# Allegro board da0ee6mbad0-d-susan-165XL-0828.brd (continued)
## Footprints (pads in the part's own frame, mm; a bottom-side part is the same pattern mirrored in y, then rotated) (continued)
CARD-CH1S-131-H-N-12P
  rect 0.66x0.991 smd: 1(2.6,9.6) 2(1.7,9.6) 3(0.8,9.6) 4(-0.1,9.6) 5(-1,9.6) 6(-1.9,9.6) 7(-2.8,9.6) 8(-3.7,9.6)
  rect 0.889x0.991 smd: 9(-5.3,9.6)
  rect 1.194x1.295 smd: 10(7.3,2.7)
  rect 0.991x1.702 smd: 11(7.2,9.25) 12(-7.2,9.25)
  oval 1.092x1.803 hole 0.508x1.194: 13(6.83,0) 14(-6.82,0)
CC0201_S
  rect 0.254x0.356 smd: 1(0.24,0) 2(-0.24,0)
CC0402
  custom 0.12x0.12 smd: 1(0.39,0) 2(-0.39,0)
CC0402_S
  rect 0.508x0.508 smd: 1(-0.42,0) 2(0.42,0)
CC0603
  rect 0.813x0.711 smd: 1(0.737,0) 2(-0.737,0)
CC0805
  rect 0.94x1.346 smd: 1(0.895,0) 2(-0.895,0)
CC1206
  rect 1.6x1.6 smd: 1(1.702,0) 2(-1.702,0)
CC3528
  rect 2.032x2.413 smd: 1(1.6,0) 2(-1.6,0)
CHOKE-1124BS-3R3M
  rect 0.991x2.21 smd: 1(-2.15,0) 2(2.15,0)
CHOKE-MMD-05AH-4R7M-X2Q
  rect 1.905x2.794 smd: 1(-2.038,0) 2(2.038,0)
CHOKE-WCM2012-4P
  rect 0.889x0.406 smd: 1(-0.85,0.4) 2(0.85,0.4) 3(0.85,-0.4) 4(-0.85,-0.4)
D-0_9X0_6
  rect 0.559x0.457 smd: 1(0,-0.475) 2(0,0.475)
D-2_8X1_78
  rect 2.21x1.397 smd: 1(-0.95,0)
  rect 0.889x1.397 smd: 2(1.6,0)
DFN6-1_5X1-5
  rect 0.254x0.991 smd: 1(-0.5,-0.567)
  rect 0.254x0.914 smd: 2(0,-0.605) 3(0.5,-0.605) 4(0.5,0.605) 5(0,0.605) 6(-0.5,0.605)
DSM
  rect 1.016x0.508 smd: 1(-1.3,0) 2(1.321,0)
DSMV
  rect 0.762x1.016 smd: 1(0,1.27) 2(0,-1.27)
EE6-SHIELDING-6
  custom 8.473x8.473 smd: 1(0,0)
EE6-SHIELDING-7
  custom 3.4x3.4 smd: 1(0,0)
EE6-SHIELDING-8
  custom 4.193x4.193 smd: 1(0,0)
EE6-SHIELDING-10
  custom 3.452x3.452 smd: 1(0,0)
  custom 0.421x0.421 smd: 2(-7.352,-14.478)
EE6-SHIELDING-11
  custom 12.781x12.781 smd: 1(0,0)
EMIPAD63X56
  custom 0.358x0.358 smd: 1(0,0)
EMIPAD98X79
  rect 2.489x2.007 smd: 1(0,0)
FH34SRJ-6S-0_5SH-6P-L
  rect 0.305x0.787 smd: 1(-1.25,2.5) 2(-0.75,2.5) 3(-0.25,2.5) 4(0.25,2.5) 5(0.75,2.5) 6(1.25,2.5)
  rect 0.406x0.787 smd: 7(-2.25,0) 8(2.25,0)
FH35C-21S-0_3SHW-21P-LDH
  rect 0.305x0.787 smd: 1(-3,-1.475) 2(-2.4,-1.475) 3(-1.8,-1.475) 4(-1.2,-1.475) 5(-0.6,-1.475) 6(0,-1.475) 7(0.6,-1.475) 8(1.2,-1.475) 9(1.8,-1.475) 10(2.4,-1.475) 11(3,-1.475)
  rect 0.305x0.66 smd: 12(2.7,1.4) 13(2.1,1.4) 14(1.5,1.4) 15(0.9,1.4) 16(0.3,1.4) 17(-0.3,1.4) 18(-0.9,1.4) 19(-1.5,1.4) 20(-2.1,1.4) 21(-2.7,1.4)
  rect 0.406x0.94 smd: 22(-3.7,-1.2) 23(3.7,-1.2)
FH35C-31S-0_3SHW-31P-LDH
  rect 0.305x0.787 smd: 1(-4.5,-1.475) 2(-3.9,-1.475) 3(-3.3,-1.475) 4(-2.7,-1.475) 5(-2.1,-1.475) 6(-1.5,-1.475) 7(-0.9,-1.475) 8(-0.3,-1.475) 9(0.3,-1.475) 10(0.9,-1.475) 11(1.5,-1.475) 12(2.1,-1.475) 13(2.7,-1.475) 14(3.3,-1.475) 15(3.9,-1.475) 16(4.5,-1.475)
  rect 0.305x0.66 smd: 17(4.2,1.4) 18(3.6,1.4) 19(3,1.4) 20(2.4,1.4) 21(1.8,1.4) 22(1.2,1.4) 23(0.6,1.4) 24(0,1.4) 25(-0.6,1.4) 26(-1.2,1.4) 27(-1.8,1.4) 28(-2.4,1.4) 29(-3,1.4) 30(-3.6,1.4) 31(-4.2,1.4)
  rect 0.406x0.94 smd: 32(-5.2,-1.2) 33(5.2,-1.2)
FILTER-LXES11DAA2-135-6P
  rect 0.305x0.508 smd: 1(0.275,0.625) 2(-0.275,0.625) 4(-0.275,-0.625) 5(0.275,-0.625)
  rect 0.406x0.203 smd: 3(-0.5,0) 6(0.5,0)
FILTER-SAFEA1G57KH0F00-5P
  rect 0.432x0.33 smd: 1(-0.588,0) 3(0.588,-0.288) 4(0.588,0.288)
  rect 0.254x0.533 smd: 2(0,-0.388) 5(0,0.388)
H-C71D71N
  round 1.803 hole 1.803 unplated: (0,0)
H-C197D79P2
  round 5.004 hole 2.007: 1(0,0)
H-C236D79P2
  round 5.994 hole 2.007: 1(0,0)
HDMI-46765-1301-19P
  rect 0.203x0.838 smd: 1(1.8,4.775) 3(1.4,4.775) 5(1,4.775) 7(0.6,4.775) 9(0.2,4.775) 11(-0.2,4.775) 13(-0.6,4.775) 15(-1,4.775) 17(-1.4,4.775) 19(-1.8,4.775)
  rect 0.203x0.991 smd: 2(1.6,3.55) 4(1.2,3.55) 6(0.8,3.55) 8(0.4,3.55) 10(0,3.55) 12(-0.4,3.55) 14(-0.8,3.55) 16(-1.2,3.55) 18(-1.6,3.55)
  oval 1.499x2.54 hole 0.66x1.702: 20(3.1,3.36) 21(3.1,0) 22(-3.1,3.36) 23(-3.1,0)
L2X1_6-1_6-1H
  rect 0.787x1.803 smd: 1(-0.8,0) 2(0.8,0)
L2X1_6-1H
  rect 0.787x1.803 smd: 1(-0.8,0) 2(0.8,0)
LED12-22-BXY2P-C31-2C-3P
  rect 0.991x1.499 smd: 1(1.5,-0.05) 3(-1.5,-0.05)
  rect 0.889x0.889 smd: 2(0,-0.7)
LEDLTW-C191DS5
  rect 0.787x0.787 smd: 1(0,-0.75) 2(0,0.75)
LGA14-5X3-8
  rect 0.61x1.397 smd: 1(2,1.3) 2(1.2,1.3) 3(0.4,1.3) 4(-0.4,1.3) 5(-1.2,1.3) 6(-2,1.3) 8(-2,-1.3) 9(-1.2,-1.3) 10(-0.4,-1.3) 11(0.4,-1.3) 12(1.2,-1.3) 13(2,-1.3)
  rect 1.702x0.635 smd: 7(-2.15,0) 14(2.15,0)
LGA16-4X4-65
  rect 0.991x0.381 smd: 1(-2,0.975) 2(-2,0.325) 3(-2,-0.325) 4(-2,-0.975) 9(2,-0.975) 10(2,-0.325) 11(2,0.325) 12(2,0.975)
  rect 0.381x0.991 smd: 5(-0.975,-2) 6(-0.325,-2) 7(0.325,-2) 8(0.975,-2) 13(0.975,2) 14(0.325,2) 15(-0.325,2) 16(-0.975,2)
MIC-MP45DT02TR-6P
  round 0.914 smd: 1(-1.175,1.65) 2(-1.175,0) 3(-1.175,-1.65) 4(1.175,-1.65) 5(1.175,0)
  oval 0.914x1.194 smd rot 135: 6(1.07,1.55)
MIPCI-APCI0026-P001A-75P-KB
  round 1.092 hole 1.092 unplated: (-11,0)
  round 1.6 hole 1.6 unplated: (11,0)
  rect 0.305x1.499 smd: 1(-9.25,1.55) 2(-9,-1.09) 3(-8.75,1.55) 4(-8.5,-1.09) 5(-8.25,1.55) 6(-8,-1.09) 7(-7.75,1.55) 8(-7.5,-1.09) 9(-7.25,1.55) 10(-7,-1.09) 11(-6.75,1.55) 20(-4.5,-1.09) 21(-4.25,1.55) 22(-4,-1.09) 23(-3.75,1.55) 24(-3.5,-1.09) 25(-3.25,1.55) 26(-3,-1.09) 27(-2.75,1.55) 28(-2.5,-1.09) 29(-2.25,1.55) 30(-2,-1.09) 31(-1.75,1.55) 32(-1.5,-1.09) 33(-1.25,1.55) 34(-1,-1.09) 35(-0.75,1.55) 36(-0.5,-1.09) 37(-0.25,1.55) 38(0,-1.09) 39(0.25,1.55) 40(0.5,-1.09) 41(0.75,1.55) 42(1,-1.09) 43(1.25,1.55) 44(1.5,-1.09) 45(1.75,1.55) 46(2,-1.09) 47(2.25,1.55) 48(2.5,-1.09) 49(2.75,1.55) 50(3,-1.09) 51(3.25,1.55) 52(3.5,-1.09) 53(3.75,1.55) 54(4,-1.09) 55(4.25,1.55) 56(4.5,-1.09) 57(4.75,1.55) 58(5,-1.09) 59(5.25,1.55) 60(5.5,-1.09) 61(5.75,1.55) 62(6,-1.09) 63(6.25,1.55) 64(6.5,-1.09) 65(6.75,1.55) 66(7,-1.09) 67(7.25,1.55) 68(7.5,-1.09) 69(7.75,1.55) 70(8,-1.09) 71(8.25,1.55) 72(8.5,-1.09) 73(8.75,1.55) 74(9,-1.09) 75(9.25,1.55)
  rect 1.194x2.743 smd: 76(-11.385,-4.97) 77(11.385,-4.97)
O-EE6-1
  custom 1.913x1.913 hole 1.803: 1(0,0)
O-EE6-2
  custom 1.5x1.5 hole 1.803: 1(0,0)
O-EE6-3
  custom 1.5x1.5 hole 2.007: 1(0,0)
O-EE6-5
  round 2.54 hole 2.54 unplated: (0,0)
OPLGA6-2_35X1_8-6
  rect 0.991x0.406 smd: 1(-1.125,0.6) 2(-1.125,0) 3(-1.125,-0.6) 4(1.125,-0.6) 5(1.125,0) 6(1.125,0.6)
PG-TSDSON-8-8P-R
  rect 0.787x0.33 smd: 1(1.5,-0.975) 2(1.5,-0.325) 3(1.5,0.325) 4(1.5,0.975)
  custom 0.573x0.573 smd: 5(-0.72,0)
  rect 0.66x0.33 smd: 6(-1.575,0.325) 7(-1.575,-0.325) 8(-1.575,-0.975)
POWER-3_3X3_3-65-5P-SMT
  rect 0.432x0.762 smd: 1(-0.975,-1.43) 2(-0.325,-1.43) 3(0.325,-1.43) 4(0.975,-1.43)
  custom 0.562x0.562 smd: 5(0,0.725)
QFN10-3X3-5-11P
  rect 0.305x0.991 smd: 1(-1,-1.6) 2(-0.5,-1.6) 3(0,-1.6) 4(0.5,-1.6) 5(1,-1.6) 6(1,1.6) 7(0.5,1.6) 8(0,1.6) 9(-0.5,1.6) 10(-1,1.6)
  custom 0.413x0.413 smd: 11(0,0)
QFN16-3X3-5-17P-TPS61176RTE
  custom 0.07x0.07 smd: 1(-0.75,-1.475) 2(-0.25,-1.475) 3(0.25,-1.475) 4(0.75,-1.475) 5(1.475,-0.75) 6(1.475,-0.25) 7(1.475,0.25) 8(1.475,0.75) 9(0.75,1.475) 10(0.25,1.475) 11(-0.25,1.475) 12(-0.75,1.475) 13(-1.475,0.75) 14(-1.475,0.25) 15(-1.475,-0.25) 16(-1.475,-0.75)
  rect 1.651x1.651 smd: 17(0,0)
QFN24-4X4-5-34P
  rect 0.838x0.279 smd: 1(-1.975,1.25) 2(-1.975,0.75) 3(-1.975,0.25) 4(-1.975,-0.25) 5(-1.975,-0.75) 6(-1.975,-1.25) 13(1.975,-1.25) 14(1.975,-0.75) 15(1.975,-0.25) 16(1.975,0.25) 17(1.975,0.75) 18(1.975,1.25)
  rect 0.279x0.838 smd: 7(-1.25,-1.975) 8(-0.75,-1.975) 9(-0.25,-1.975) 10(0.25,-1.975) 11(0.75,-1.975) 12(1.25,-1.975) 19(1.25,1.975) 20(0.75,1.975) 21(0.25,1.975) 22(-0.25,1.975) 23(-0.75,1.975) 24(-1.25,1.975)
  rect 2.692x2.692 smd: 25(0,0)
  round 0.61 hole 0.305: 26(-0.9,0.9) 27(-0.9,0) 28(-0.9,-0.9) 29(0,-0.9) 30(0.9,-0.9) 31(0.9,0) 32(0.9,0.9) 33(0,0.9) 34(0,0)
QFN48-6X6-4-49P-ALC280
  rect 0.991x0.203 smd: 1(-3.1,2.2) 2(-3.1,1.8) 3(-3.1,1.4) 4(-3.1,1) 5(-3.1,0.6) 6(-3.1,0.2) 7(-3.1,-0.2) 8(-3.1,-0.6) 9(-3.1,-1) 10(-3.1,-1.4) 11(-3.1,-1.8) 12(-3.1,-2.2) 25(3.1,-2.2) 26(3.1,-1.8) 27(3.1,-1.4) 28(3.1,-1) 29(3.1,-0.6) 30(3.1,-0.2) 31(3.1,0.2) 32(3.1,0.6) 33(3.1,1) 34(3.1,1.4) 35(3.1,1.8) 36(3.1,2.2)
  rect 0.203x0.991 smd: 13(-2.2,-3.1) 14(-1.8,-3.1) 15(-1.4,-3.1) 16(-1,-3.1) 17(-0.6,-3.1) 18(-0.2,-3.1) 19(0.2,-3.1) 20(0.6,-3.1) 21(1,-3.1) 22(1.4,-3.1) 23(1.8,-3.1) 24(2.2,-3.1) 37(2.2,3.1) 38(1.8,3.1) 39(1.4,3.1) 40(1,3.1) 41(0.6,3.1) 42(0.2,3.1) 43(-0.2,3.1) 44(-0.6,3.1) 45(-1,3.1) 46(-1.4,3.1) 47(-1.8,3.1) 48(-2.2,3.1)
  rect 4.394x4.394 smd: 49(0,0)
QFN48-7X7-5-49P-STM32F103CB
  rect 0.559x0.305 smd: 1(-3.375,2.75) 2(-3.375,2.25) 3(-3.375,1.75) 4(-3.375,1.25) 5(-3.375,0.75) 6(-3.375,0.25) 7(-3.375,-0.25) 8(-3.375,-0.75) 9(-3.375,-1.25) 10(-3.375,-1.75) 11(-3.375,-2.25) 12(-3.375,-2.75) 25(3.375,-2.75) 26(3.375,-2.25) 27(3.375,-1.75) 28(3.375,-1.25) 29(3.375,-0.75) 30(3.375,-0.25) 31(3.375,0.25) 32(3.375,0.75) 33(3.375,1.25) 34(3.375,1.75) 35(3.375,2.25) 36(3.375,2.75)
  rect 0.305x0.559 smd: 13(-2.75,-3.375) 14(-2.25,-3.375) 15(-1.75,-3.375) 16(-1.25,-3.375) 17(-0.75,-3.375) 18(-0.25,-3.375) 19(0.25,-3.375) 20(0.75,-3.375) 21(1.25,-3.375) 22(1.75,-3.375) 23(2.25,-3.375) 24(2.75,-3.375) 37(2.75,3.375) 38(2.25,3.375) 39(1.75,3.375) 40(1.25,3.375) 41(0.75,3.375) 42(0.25,3.375) 43(-0.25,3.375) 44(-0.75,3.375) 45(-1.25,3.375) 46(-1.75,3.375) 47(-2.25,3.375) 48(-2.75,3.375)
  rect 5.588x5.588 smd: 49(0,0)
RC0201_S
  rect 0.254x0.356 smd: 1(0.24,0) 2(-0.24,0)
RC0402
  custom 0.12x0.12 smd: 1(0.39,0) 2(-0.39,0)
RC0402_S
  rect 0.508x0.508 smd: 1(-0.42,0) 2(0.42,0)
RC0603
  rect 0.813x0.711 smd: 1(0.737,0) 2(-0.737,0)
RC0805_S
  rect 0.864x1.372 smd: 1(-0.88,0) 2(0.88,0)
RC3216
  rect 3.2x0.94 smd: 1(0,0.825) 2(0,-0.825)
SC70-2_1-65-6P
  rect 1.27x0.279 smd: 1(1.02,-0.65) 2(1.02,0) 3(1.02,0.65) 4(-1.02,0.65) 5(-1.02,0) 6(-1.02,-0.65)
SHORT0201_S
  rect 0.432x0.356 smd: 1(0.24,0) 2(-0.24,0)
SHORT0402
  rect 0.648x0.5 smd: 1(-0.39,0) 2(0.39,0)
SHORT0402_S
  rect 0.737x0.508 smd: 1(-0.42,0) 2(0.42,0)
SHORT0603
  rect 1.219x0.711 smd: 1(0.737,0) 2(-0.737,0)
SHORT0805
  rect 1.422x1.346 smd: 1(0.895,0) 2(-0.895,0)
SIMCARD-159-1000302603-10P-L
  round 0.889 hole 0.889 unplated: (4.94,7.9) (5.64,-3.2)
  rect 0.508x1.245 smd: 1(-3.545,9.325) 2(-2.845,9.325) 3(-2.145,9.325) 4(-1.445,9.325) 5(-0.745,9.325) 6(-0.045,9.325) 7(0.655,9.325) 8(1.355,9.325) 9(2.055,9.325) 10(2.755,9.325)
  rect 0.889x1.397 smd: 11(5.41,9.4) 18(-4.7,9.4)
  rect 0.381x1.6 smd: 12(7.165,6.85)
  rect 0.381x1.499 smd: 13(7.165,0) 16(-7.165,0)
  rect 1.092x1.092 smd: 14(6.8,-5.32) 15(-6.8,-5.32)
  rect 0.381x1.245 smd: 17(-7.165,6.24)
SOIC8-8-1_27
  rect 0.533x1.6 smd: 1(1.905,3.8) 2(0.635,3.8) 3(-0.635,3.8) 4(-1.905,3.8) 5(-1.905,-3.8) 6(-0.635,-3.8) 7(0.635,-3.8) 8(1.905,-3.8)
SOT23-2_8-95-5P-1_45H
  rect 0.508x1.321 smd: 1(-0.95,-1.338) 2(0,-1.338) 3(0.95,-1.338) 4(0.95,1.338) 5(-0.95,1.338)
SOT23-5
  rect 1.016x0.711 smd: 1(1.2,-0.95) 2(1.2,0) 3(1.2,0.95) 4(-1.2,0.95) 5(-1.2,-0.95)
SOT23-5-2_8-95-5P-1_3H
  rect 1.194x0.533 smd: 1(1.5,-0.95) 2(1.5,0) 3(1.5,0.95) 4(-1.5,0.95) 5(-1.5,-0.95)
SOT23_123-2_8-1_9
  rect 1.092x0.533 smd: 1(1.45,-0.95) 2(1.45,0.95) 3(-1.45,0)
SOT23_213-3_3-2
  rect 1.27x1.016 smd: 1(1.016,1.016) 2(1.016,-1.016) 3(-1.016,0)
SW-MTA-NC-V-T-R-5P
  round 0.889 hole 0.889 unplated: (-2.15,0) (2.15,0)
  custom 0.178x0.178 smd: 1(2.1,0.95) 2(-2.1,0.95)
  rect 0.711x1.194 smd: 3(1.7,-1.3) 5(-1.7,-1.3)
  rect 1.295x0.787 smd: 4(0,-1.5)
TDFN8-3X3-65-9P
  rect 0.381x0.94 smd: 1(-0.975,-1.625) 2(-0.325,-1.625) 3(0.325,-1.625) 4(0.975,-1.625) 5(0.975,1.625) 6(0.325,1.625) 7(-0.325,1.625) 8(-0.975,1.625)
  rect 2.311x1.499 smd: 9(0,0)
TP2050
  round 0.508 smd: 1(0,0)
TP2650
  round 0.66 smd: 1(0,0)
TQFN10-1_6X1_3-4
  rect 0.203x0.711 smd: 1(0.2,0.46) 2(-0.2,0.46) 6(-0.2,-0.46) 7(0.2,-0.46)
  rect 0.508x0.203 smd: 3(-0.735,0.4) 4(-0.735,0) 5(-0.735,-0.4) 8(0.735,-0.4) 9(0.735,0) 10(0.735,0.4)
UFDFPN8-2X3-5-9P
  rect 0.305x1.194 smd: 1(-0.75,-1.35) 2(-0.25,-1.35) 3(0.25,-1.35) 4(0.75,-1.35) 5(0.75,1.35) 6(0.25,1.35) 7(-0.25,1.35) 8(-0.75,1.35)
  rect 1.6x0.203 smd: 9(0,0)
unnamed
  round 1.016 smd: 1(0,0)
UQFN10-2X1_5-5-0_6H
  rect 0.305x0.584 smd: 1(-0.75,-0.638) 4(0.75,-0.638) 6(0.75,0.638) 9(-0.75,0.638)
  rect 0.254x0.584 smd: 2(-0.25,-0.638) 3(0.25,-0.638) 7(0.25,0.638) 8(-0.25,0.638)
  rect 0.635x0.356 smd: 5(0.86,0) 10(-0.86,0)
VMT3-1_2-8
  rect 0.457x0.406 smd: 1(0.575,-0.4) 2(0.575,0.4)
  rect 0.508x0.457 smd: 3(-0.575,0)
VSSOP8-3_1-5-8P
  rect 0.203x1.168 smd: 1(-0.75,-1.563) 2(-0.25,-1.563) 3(0.25,-1.563) 4(0.75,-1.563) 5(0.75,1.563) 6(0.25,1.563) 7(-0.25,1.563) 8(-0.75,1.563)
XTL-2_1X1_7-1_94X1_19
  rect 0.432x0.787 smd: 1(-0.97,-0.595) 2(0.97,-0.595) 3(0.97,0.595) 4(-0.97,0.595)
XTL-3_2X1_5-2_5-0_8H
  rect 0.991x1.803 smd: 1(-1.25,0) 2(1.25,0)
XTL-3_2X2_5-2_2X1_7
  rect 1.397x1.194 smd: 1(1.1,0.85) 2(-1.1,0.85) 3(-1.1,-0.85) 4(1.1,-0.85)
XTL-3_2X2_5-2_2X1_7-4P
  rect 1.397x1.194 smd: 1(1.1,0.85) 2(-1.1,0.85) 3(-1.1,-0.85) 4(1.1,-0.85)

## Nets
+1.8V_EMMC: C8.2 C188.2 C196.2 C200.1 C204.1 R275.2 U26.AA3 U26.AA5 U26.K6 U26.W4 U26.Y4
+1V: PC45.2 PQ8.1 PQ8.2 PQ8.3 PR58.2 PR63.1 PR64.1 PR65.1 PR81.2 PR83.1 PR84.1 PR666.1 R56.2 R77.1 R297.2 R327.1
+1V05: PC94.1 PL13.1 PU5.P8 R292.1 R295.1
+1V05_SOC: C27.1 C30.1 C259.1 C261.1 C263.1 R292.2 R295.2 U29.A30 U29.A33 U29.A35 U29.AC37 U29.AD36 U29.AK39 U29.B36 U29.BW39 U29.W39
+1V8: C298.1 C319.1 C375.1 CN2.9 L5.2 PC17.1 PR1.1 PR96.1 PR109.1 PR110.1 PR111.1 PR112.1 PU5.B9 Q2.1 Q3.1 Q7.2 Q8.2 Q17.1 R14.1 R15.1 R47.1 R53.1 R73.1 R74.1 R80.1 R93.2 R115.1 R117.2 R119.2 R160.1 R168.2 R170.2 R175.2 R177.2 R183.2 R187.1 R262.2 R275.1 R290.1 R291.1 R293.1 R303.2 R305.2 R335.2 R337.1 R340.2 R342.2 R345.2 R353.1 R359.2 R362.2 U31.2 U33.2 U37.2
+1V8_SOC: C26.1 C31.1 C262.1 C269.1 R47.2 U29.BF36 U29.BV22 U29.BV32 U29.BW21 U29.BW33 U29.P42
+1V8S5: C25.2 C77.2 PC15.1 PC82.2 PC83.2 PC84.2 PL12.2 PR20.2 PU5.B8 PU5.C9 PU5.G1 R17.1 R18.1 R26.2 R27.1 R29.1 R37.2 R38.1 R41.1 R46.1 R84.2 R134.2 R135.2 R136.2 R166.1 R298.2 R302.2 R313.1 R328.2 R332.2 R333.2 U3.C2 U5.A2
+1V8S5_SOC: C43.1 C47.1 C67.1 C282.1 R37.1 R306.2 R307.2 R402.2 U29.AD15 U29.G1 U29.P21 U29.P23 U29.P27
+1V8SX: PC9.1 PR44.1 PU5.B7 R1.2 R216.1 R220.1 R223.1 R230.2
+1V24: PC77.1 PU5.C10 R70.1 R71.1 R315.2
+1V24_SOC: C277.1 R315.1 U29.AF2 U29.AG1
+1V24S5: PC70.1 PU5.C7 R320.2
+1V24S5_SOC: C284.1 R320.1 U29.R1
+1V24SX: PC23.1 PU5.B10 R76.1 R81.1 R82.1
+1V24SX_SOC: C21.1 R76.2 U29.AK45
+1V_SOC: C32.1 C35.1 C62.1 C278.1 C280.1 C281.1 C283.1 C286.1 C289.1 R327.2 U29.AA1 U29.AN1 U29.AP2 U29.BF32 U29.M36 U29.N1 U29.P2
+1VS5: PC18.1 PC47.2 PC48.2 PC53.2 PC97.1 PC98.1 PL15.1 PQ7.5 PQ8.5 PQ9.5 PU5.C11 PU5.M10 R78.1
+1VS5_SOC: C59.1 C64.1 C285.1 R78.2 U29.P15 U29.P17 U29.P19 U29.T18 U29.W1
+1VSX: C72.1 C73.1 C74.1 PC46.2 PQ9.1 PQ9.2 PQ9.3 PR60.2 R59.1 R299.1 R300.1 R667.1
+1VSX_S: PC44.2 PQ7.1 PQ7.2 PQ7.3 PR666.2 R309.1 R310.1 R667.2
+1VSX_S_SOC: C24.2 C255.1 C256.1 C257.1 C258.1 R309.2 R310.2 U29.A41 U29.A43 U29.AC43 U29.AH44 U29.AW44 U29.B40 U29.BV40 U29.BW41 U29.BW43
+1VSX_SOC: C61.1 C264.2 C265.1 C272.1 C273.1 C279.1 R299.2 R300.2 U29.A9 U29.A13 U29.AT19 U29.AT21 U29.AV2 U29.AW1 U29.AW15 U29.B10 U29.B14 U29.BV26 U29.BW27
+2.85V_EMMC: C4.2 C5.1 C7.1 C9.2 C10.2 R16.2 U26.M6 U26.N5 U26.T10 U26.U9
+2V8_CAM: PC41.1 PU2.5 R194.2 R215.1 R222.2 R228.2
+2V85: PC26.1 PC99.2 PC100.2 PC101.2 PC102.2 PC103.2 PU5.C15 PU5.E13 PU5.F13 R16.1
+3.3V_PA: C132.1 C365.2 C366.2 C367.2 R189.2 R192.2 U36.G9
+3V3: CN1.16 CN2.10 PC120.2 PQ2.1 PQ11.5 PQ11.6 PQ11.7 PQ11.8 PU5.G13 Q22.1 R7.2 R57.1 R58.1 R158.2 R181.1 R182.1 R184.2 R195.1 R196.1 R208.2 R218.2 R263.2 R304.1 R339.2 R364.1 R366.2 R370.2 R386.1 R404.1 R406.2 R407.2 R410.1 R663.1 R664.1
+3V3_LCM: C48.2 C55.1 CN9.6 CN9.7 Q22.3 R663.2 R673.1 R674.1
+3V3_LS: C3.1 R3.1 R7.1 U1.6
+3V3_NGFF: C153.1 C154.1 C155.1 C156.1 C157.1 C158.1 C221.1 C226.1 CN7.2 CN7.4 CN7.70 CN7.72 CN7.74 PC42.2 PQ6.5 PQ6.6 PQ6.7 PQ6.8 R278.1
+3V3_SD_SW: C126.2 C127.1 CN4.4 PQ2.3 R184.1
+3V3PCU: C108.1 D7.2 HE1.1 LED1.1 PR30.1 PR116.2 PR120.1 PR124.2 PR129.2 PR139.2 R111.2 R148.1 R151.2 R161.1 R167.2 R171.2 R193.1 R199.1 R408.2 TP19.1
+3V3S5: C295.2 CN1.25 PC3.1 PC10.1 PC43.1 PC111.2 PC112.2 PC113.2 PC114.2 PC115.2 PC116.2 PC117.2 PC128.2 PQ11.1 PQ11.2 PQ11.3 PR57.1 PR61.1 PR153.2 PU2.1 PU3.2 PU5.C5 PU5.F12 PU5.F15 PU5.G3 PU5.G14 R43.2 R137.2 R138.2 R139.2 R140.2 R141.2 R669.1 R670.2
+3V3S5_SOC: C56.1 C57.1 C58.1 R43.1 U29.M20
+3V3SX: C296.2 PU3.6 PU3.7 R319.1
+3VPCU_EC: C110.2 C112.1 C113.1 C118.1 C119.1 C120.1 L3.1 R164.2 U12.D4 U12.D5 U12.E6 U12.F5 U12.F6
+3VPCU_EC_PWR: C121.1 C123.2 R164.1 R408.1 U12.F4
+5V: C87.2 PC137.2 PQ12.5 PQ12.6 PQ12.7 PQ12.8 PR12.1 PR151.2 R101.1 R186.1 R355.1 R373.2 U7.8
+5V_SRC: PC105.1 PC106.1 PC107.1 PC108.1 PC109.1 PC110.1 PQ12.1 PQ12.2 PQ12.3 PR151.1 PR152.1 PU5.L14 PU5.L15 PU5.M12
+A3VPCU: C122.1 C124.1 L3.2 U12.B1
+V1.0S_GPIO: C69.2 R56.1 R159.1 U29.BB2 U29.BB15 U29.BC1 U29.BD14 U29.BF2 U29.BG1
+V1.0S_GUIO: C65.2 C75.2 R77.2 U29.M14
+V1.0SX_DIGDP: C66.1 C71.2 R59.2 U29.AU14
+V1.8S_2M_F: C1.1 C2.1 CN5.20 R1.1
+V1.8S_5M_R: C161.1 C162.1 CN6.13 R230.1
+V1.8U_LPDDR3: C11.2 C13.2 C14.2 C16.2 C170.2 C179.2 C193.2 C194.2 R17.2 U23.A15 U23.A16 U23.B2 U23.R1 U23.T1 U23.T16 U24.A15 U24.A16 U24.B2 U24.R1 U24.T1 U24.T16
+V2.8_2M_F: C135.1 C136.1 CN5.21 R194.1
+V2.8_5M_R: C159.1 C160.2 CN6.12 R228.1
+V3.3_VUSB2: C292.1 R319.2 U29.J1 U29.K2
+V3.3A_SRC: PC124.1 PC129.2 PC130.2 PR120.2 PR143.2 PU8.1
+V3.3S_ACCEL: C356.1 C357.1 C358.2 R386.2 U35.1 U35.14
+V3.3S_GYRO: C300.1 C301.2 R339.1 R344.2 R348.1 U32.15 U32.16
+V3.3S_SENSOR: C103.1 L1.2 R116.1 R130.1 R133.1 R145.1 R146.1 R154.1 R155.1 R157.1 R158.1 R336.2 R338.1 R341.2 R343.2 RP1.2 RP1.4 U10.9
+VBAT_R: C98.2 C99.2 C100.2 C101.2 C105.1 L1.1 U10.1 U10.24 U10.36 U10.48
+VBATBKUP: PC6.2 PR4.1 R113.1
+VDDQ: C17.2 C18.2 C20.1 C22.1 C171.2 C172.2 C173.2 C174.2 C175.2 C176.2 C177.2 C178.2 C181.2 C182.2 C201.2 C202.2 C212.2 C213.2 C217.2 C218.2 C219.2 C220.2 C222.2 C224.2 C227.2 C228.2 C230.2 C232.2 C234.2 C235.2 C236.2 C237.2 C238.2 C239.2 C240.2 C241.2 C242.2 C243.2 C244.1 C245.1 C246.1 C247.1 C248.1 C249.1 C250.1 C251.1 C757.2 C758.2 PC12.1 PC14.1 PC89.1 PC90.1 PC91.1 PL14.2 PU5.A10 PU5.D11 PU5.D12 R21.2 R22.1 R23.1 R239.1 R240.1 U23.A6 U23.A7 U23.A9 U23.A11 U23.A13 U23.B9 U23.B12 U23.B17 U23.C3 U23.C12 U23.C17 U23.E1 U23.E17 U23.G2 U23.G12 U23.G17 U23.H1 U23.H16 U23.K1 U23.K12 U23.K17 U23.L1 U23.L17 U23.M2 U23.M3 U23.M7 U23.M10 U23.M12 U23.N1 U23.P17 U23.R15 U23.T8 U23.U2 U23.U3 U23.U5 U23.U7 U23.U10 U23.U11 U23.U14 U24.A6 U24.A7 U24.A9 U24.A11 U24.A13 U24.B9 U24.B12 U24.B17 U24.C3 U24.C12 U24.C17 U24.E1 U24.E17 U24.G2 U24.G12 U24.G17 U24.H1 U24.H16 U24.K1 U24.K12 U24.K17 U24.L1 U24.L17 U24.M2 U24.M3 U24.M7 U24.M10 U24.M12 U24.N1 U24.P17 U24.R15 U24.T8 U24.U2 U24.U3 U24.U5 U24.U7 U24.U10 U24.U11 U24.U14 U29.AA59 U29.AC45 U29.AC59 U29.AE59 U29.AR59 U29.AU59 U29.AW59 U29.BA45 U29.BA59 U29.BG59 U29.BJ59 U29.BL59 U29.BN59 U29.G59 U29.J59 U29.L59 U29.N59 U29.W59
+VDDQ_VTT: C164.2 C165.2 C166.2 C167.2 C168.2 C169.2 C189.2 C190.2 PC95.1 PU5.C12 PU5.C14 R243.1 R244.1 R245.1 R246.1 R247.1 R248.1 R249.1 R250.1 R251.1 R252.1 R254.1 R255.1 R264.1 R265.1 R267.1 R268.1 R269.1 R270.1 R272.1 R273.1
AGND: C321.1 C322.2 C327.2 C332.1 C333.2 C335.2 C336.1 C337.2 C338.2 C340.1 C343.1 C344.2 C345.2 C346.1 C347.2 C348.2 C349.2 C354.2 C355.1 CN13.15 L15.1 L17.1 L19.1 L25.1 L26.1 R379.2 R380.2 R382.1 U34.9 U34.22
AVDD_ADO: C340.2 C348.1 L16.1 R381.2 U34.15
GND: C1.2 C2.2 C3.2 C4.1 C5.2 C6.2 C7.2 C8.1 C9.1 C10.1 C11.1 C12.1 C13.1 C14.1 C15.1 C16.1 C17.1 C18.1 C19.1 C20.2 C21.2 C22.2 C23.2 C24.1 C25.1 C26.2 C27.2 C28.2 C29.1 C30.2 C31.2 C32.2 C33.1 C34.1 C35.2 C36.2 C37.2 C38.2 C39.1 C40.2 C41.2 C42.1 C43.2 C44.2 C45.2 C46.2 C47.2 C48.1 C49.1 C50.2 C51.1 C52.1 C53.2 C54.1 C55.2 C56.2 C57.2 C58.2 C59.2 C60.2 C61.2 C62.2 C64.2 C65.1 C66.2 C67.2 C68.2 C69.1 C70.2 C71.1 C72.2 C73.2 C74.2 C75.1 C76.1 C77.1 C78.1 C79.2 C80.1 C81.2 C82.2 C87.1 C88.2 C92.1 C94.2 C95.1 C96.1 C97.1 C98.1 C99.1 C100.1 C101.1 C102.2 C103.2 C104.2 C105.2 C106.2 C107.2 C108.2 C109.1 C110.1 C111.2 C112.2 C113.2 C114.1 C115.2 C116.1 C117.2 C118.2 C119.2 C120.2 C121.2 C123.1 C125.1 C126.1 C127.2 C128.2 C129.2 C130.2 C131.2 C132.2 C133.2 C134.2 C135.2 C136.2 C137.2 C138.1 C139.2 C140.1 C141.1 C142.1 C143.2 C144.2 C145.2 C146.1 C147.1 C148.2 C149.2 C150.1 C151.1 C152.1 C153.2 C154.2 C155.2 C156.2 C157.2 C158.2 C159.2 C160.1 C161.2 C162.2 C163.2 C164.1 C165.1 C166.1 C167.1 C168.1 C169.1 C170.1 C171.1 C172.1 C173.1 C174.1 C175.1 C176.1 C177.1 C178.1 C179.1 C180.1 C181.1 C182.1 C183.1 C184.1 C185.2 C186.2 C187.2 C188.1 C189.1 C190.1 C191.2 C192.2 C193.1 C194.1 C195.2 C196.1 C197.1 C198.2 C199.2 C200.2 C201.1 C202.1 C203.1 C204.2 C205.2 C206.1 C207.1 C209.2 C210.1 C211.2 C212.1 C213.1 C214.1 C215.2 C216.1 C217.1 C218.1 C219.1 C220.1 C221.2 C222.1 C223.2 C224.1 C225.1 C226.2 C227.1 C228.1 C230.1 C231.2 C232.1 C234.1 C235.1 C236.1 C237.1 C238.1 C239.1 C240.1 C241.1 C242.1 C243.1 C244.2 C245.2 C246.2 C247.2 C248.2 C249.2 C250.2 C251.2 C252.1 C254.1 C255.2 C256.2 C257.2 C258.2 C259.2 C260.2 C261.2 C262.2 C263.2 C264.1 C265.2 C266.2 C267.2 C268.2 C269.2 C270.2 C271.2 C272.2 C273.2 C274.1 C275.1 C276.1 C277.2 C278.2 C279.2 C280.2 C281.2 C282.2 C283.2 C284.2 C285.2 C286.2 C287.2 C288.1 C289.2 C290.2 C291.2 C292.2 C293.2 C294.2 C295.1 C296.1 C297.1 C298.2 C299.1 C300.2 C301.1 C302.2 C303.2 C304.2 C305.1 C306.2 C307.2 C308.2 C309.2 C310.1 C311.2 C312.1 C313.2 C314.2 C315.1 C316.1 C317.1 C318.2 C319.2 C320.1 C323.1 C324.1 C325.1 C326.1 C328.1 C330.1 C331.1 C350.1 C351.1 C352.1 C353.1 C356.2 C357.2 C358.1 C360.2 C361.1 C362.2 C363.2 C364.1 C365.1 C366.1 C367.1 C368.2 C369.1 C370.2 C371.2 C372.1 C375.2 C376.1 C377.1 C378.1 C437.1 C447.1 C452.1 C458.1 C466.1 C756.1 C757.1 C758.1 CN1.15 CN1.22 CN1.30 CN1.31 CN1.52 CN1.61 CN1.62 CN1.63 CN1.64 CN2.8 CN2.11 CN2.12 CN3.4 CN3.7 CN3.10 CN3.13 CN3.16 CN3.20 CN3.21 CN3.22 CN3.23 CN4.6 CN4.10 CN4.11 CN4.12 CN4.13 CN4.14 CN5.1 CN5.3 CN5.4 CN5.9 CN5.12 CN5.15 CN5.22 CN5.23 CN6.3 CN6.8 CN6.9 CN6.11 CN6.18 CN6.21 CN6.22 CN6.23 CN7.3 CN7.5 CN7.11 CN7.27 CN7.33 CN7.39 CN7.45 CN7.51 CN7.57 CN7.71 CN7.73 CN8.2 CN8.3 CN8.4 CN9.11 CN9.17 CN9.20 CN9.23 CN9.26 CN9.29 CN9.32 CN9.33 CN10.9 CN10.10 CN11.1 CN11.7 CN11.8 CN12.5 CN12.6 CN13.6 CN13.9 CN13.12 CN13.13 CN14.2 CN14.3 CN14.4 CN15.2 CN15.3 CN15.4 CT1.1 CT2.1 D3.2 D4.2 D7.1 D8.1 D9.2 F1.2 HE1.3 HOLE3.1 HOLE4.1 HOLE5.1 HOLE6.1 HOLE7.1 HOLE8.1 HOLE9.1 HOLE10.1 HOLE10.2 HOLE11.1 J1.8 J1.11 J1.12 J1.13 J1.14 J1.15 J1.16 J1.17 J1.18 L15.2 L17.2 L19.2 L25.2 L26.2 L28.2 L29.2 L30.2 L31.2 PC1.2 PC2.2 PC3.2 PC4.2 PC5.1 PC6.1 PC7.2 PC8.2 PC9.2 PC10.2 PC11.2 PC12.2 PC13.2 PC14.2 PC15.2 PC16.2 PC17.2 PC18.2 PC19.1 PC20.2 PC21.2 PC22.2 PC23.2 PC24.2 PC25.2 PC26.2 PC27.2 PC28.2 PC29.1 PC30.1 PC32.2 PC33.1 PC34.2 PC35.2 PC36.1 PC37.1 PC38.1 PC39.2 PC40.2 PC41.2 PC42.1 PC43.2 PC44.1 PC45.1 PC46.1 PC47.1 PC48.1 PC49.1 PC50.1 PC51.1 PC52.1 PC53.1 PC54.2 PC55.2 PC56.2 PC57.2 PC58.1 PC59.1 PC60.2 PC61.2 PC62.2 PC63.2 PC64.2 PC65.2 PC66.2 PC67.2 PC68.2 PC69.2 PC70.2 PC71.1 PC72.2 PC73.1 PC75.2 PC76.2 PC77.2 PC78.2 PC79.2 PC80.2 PC81.1 PC82.1 PC83.1 PC84.1 PC85.2 PC86.1 PC87.2 PC88.2 PC89.2 PC90.2 PC91.2 PC92.2 PC93.1 PC94.2 PC95.2 PC96.2 PC97.2 PC98.2 PC99.1 PC100.1 PC101.1 PC102.1 PC103.1 PC104.1 PC105.2 PC106.2 PC107.2 PC108.2 PC109.2 PC110.2 PC111.1 PC112.1 PC113.1 PC114.1 PC115.1 PC116.1 PC117.1 PC118.1 PC120.1 PC122.2 PC123.1 PC124.2 PC125.2 PC126.1 PC127.1 PC128.1 PC129.1 PC130.1 PC131.1 PC132.1 PC133.1 PC135.2 PC136.1 PC137.1 PD1.2 PD3.2 PD4.2 PQ3.1 PQ5.1 PQ13.1 PR6.1 PR14.1 PR16.1 PR17.1 PR22.2 PR34.1 PR38.2 PR43.1 PR47.2 PR55.2 PR75.2 PR91.1 PR99.2 PR108.2 PR115.2 PR130.1 PR132.2 PR134.2 PR135.1 PR147.1 PR148.1 PU1.C1 PU1.C2 PU2.2 PU3.1 PU4.2 PU4.4 PU5.A6 PU5.A7 PU5.A13 PU5.A15 PU5.B2 PU5.B3 PU5.B13 PU5.B14 PU5.B15 PU5.C2 PU5.C3 PU5.C8 PU5.C13 PU5.D15 PU5.F1 PU5.G10 PU5.G11 PU5.G12 PU5.H15 PU5.J1 PU5.K1 PU5.L6 PU5.N2 PU5.N3 PU5.N14 PU5.N15 PU5.P2 PU5.P3 PU5.P6 PU5.P7 PU5.P13 PU5.P15 PU5.R6 PU5.R9 PU5.R13 PU5.R14 PU5.R15 PU6.5 PU6.6 PU6.7 PU6.8 PU6.13 PU7.17 PU7.18 PU7.25 PU7.26 PU7.27 PU7.28 PU7.29 PU7.30 PU7.31 PU7.32 PU7.33 PU7.34 PU8.3 PU8.9 PU8.11 Q1.1 Q1.4 Q4.2 Q5.2 Q6.2 Q9.1 Q9.4 Q10.1 Q10.4 Q11.1 Q11.4 Q12.2 Q13.2 Q14.1 Q14.4 Q15.2 Q16.2 Q18.1 Q18.4 Q23.2 Q24.1 Q24.4 R9.2 R19.2 R20.2 R24.1 R28.1 R30.2 R31.2 R32.2 R36.2 R39.1 R40.1 R44.1 R49.1 R50.1 R62.1 R63.1 R64.1 R65.1 R66.1 R67.2 R68.1 R90.1 R94.2 R112.1 R121.1 R122.1 R123.1 R124.1 R125.1 R126.1 R127.1 R128.1 R129.2 R142.2 R143.2 R144.2 R147.2 R153.2 R156.2 R159.2 R176.2 R190.2 R206.2 R224.2 R225.2 R227.2 R231.1 R232.1 R233.1 R234.1 R235.1 R238.2 R241.2 R260.2 R276.1 R279.1 R281.1 R283.1 R285.1 R286.1 R289.1 R296.1 R317.2 R318.2 R321.1 R322.1 R323.1 R330.2 R331.2 R334.1 R349.1 SS1.2 SW1.1 SW1.2 SW1.3 SW1.4 SW2.1 SW2.2 SW2.3 SW2.4 SW3.1 SW3.2 SW3.3 SW3.4 SW4.1 SW4.2 SW4.3 SW4.4 T1.1 T2.1 T3.1 T4.2 T5.2 T6.1 T7.1 T8.1 T9.1 T10.2 T11.2 T12.2 T13.2 T14.2 T15.2 T16.2 T17.2 T18.1 TP30.1 TP67.1 TP68.1 TP69.1 U1.1 U2.1 U2.3 U3.C3 U3.C4 U4.3 U4.6 U5.C1 U7.3 U7.5 U8.C3 U8.C4 U10.8 U10.23 U10.35 U10.47 U11.3 U11.8 U12.A2 U12.D6 U12.E4 U13.2 U14.C1 U15.3 U15.6 U16.3 U16.6 U17.3 U17.6 U18.3 U18.6 U19.2 U19.9 U20.2 U20.9 U21.3 U21.6 U22.B4 U22.C4 U22.C5 U22.C6 U22.D2 U22.D5 U23.A2 U23.A3 U23.A4 U23.A5 U23.A8 U23.A12 U23.A14 U23.B1 U23.B3 U23.B4 U23.C1 U23.C2 U23.C4 U23.D1 U23.D2 U23.D3 U23.D4 U23.D12 U23.D17 U23.E5 U23.E6 U23.E7 U23.E8 U23.E9 U23.E10 U23.E11 U23.E12 U23.F1 U23.F5 U23.F12 U23.F17 U23.G1 U23.G5 U23.G15 U23.G16 U23.H5 U23.H12 U23.H15 U23.J5 U23.J17 U23.K5 U23.L5 U23.L12 U23.M1 U23.M4 U23.M5 U23.M6 U23.M8 U23.M11 U23.M17 U23.N13 U23.N17 U23.P1 U23.P14 U23.R7 U23.R8 U23.R16 U23.R17 U23.T7 U23.T15 U23.T17 U23.U4 U23.U6 U23.U9 U23.U12 U23.U13 U23.U15 U23.U16 U24.A2 U24.A3 U24.A4 U24.A5 U24.A8 U24.A12 U24.A14 U24.B1 U24.B3 U24.B4 U24.C1 U24.C2 U24.C4 U24.D1 U24.D2 U24.D3 U24.D4 U24.D12 U24.D17 U24.E5 U24.E6 U24.E7 U24.E8 U24.E9 U24.E10 U24.E11 U24.E12 U24.F1 U24.F5 U24.F12 U24.F17 U24.G1 U24.G5 U24.G15 U24.G16 U24.H5 U24.H12 U24.H15 U24.J5 U24.J17 U24.K5 U24.L5 U24.L12 U24.M1 U24.M4 U24.M5 U24.M6 U24.M8 U24.M11 U24.M17 U24.N13 U24.N17 U24.P1 U24.P14 U24.R7 U24.R8 U24.R16 U24.R17 U24.T7 U24.T15 U24.T17 U24.U4 U24.U6 U24.U9 U24.U12 U24.U13 U24.U15 U24.U16 U25.2 U25.3 U25.5 U26.AA4 U26.AA6 U26.K4 U26.M7 U26.P5 U26.R10 U26.U8 U26.Y2 U26.Y5 U27.1 U27.2 U28.2 U28.3 U28.5 U29.A3 U29.A5 U29.A7 U29.A11 U29.A15 U29.A27 U29.A37 U29.A39 U29.A45 U29.A47 U29.A49 U29.A51 U29.A53 U29.A55 U29.A57 U29.AA7 U29.AA11 U29.AA15 U29.AA23 U29.AA27 U29.AA29 U29.AA38 U29.AA40 U29.AA42 U29.AA46 U29.AB2 U29.AB6 U29.AB12 U29.AB52 U29.AB58 U29.AC1 U29.AC7 U29.AC14 U29.AC18 U29.AC24 U29.AC28 U29.AC31 U29.AC39 U29.AC41 U29.AC49 U29.AC53 U29.AD2 U29.AD6 U29.AD8 U29.AD17 U29.AD23 U29.AD38 U29.AD40 U29.AD42 U29.AD44 U29.AD46 U29.AD52 U29.AD54 U29.AD56 U29.AE7 U29.AE11 U29.AF6 U29.AF12 U29.AF16 U29.AF18 U29.AF24 U29.AF28 U29.AF31 U29.AF37 U29.AF41 U29.AF43 U29.AF45 U29.AF54 U29.AF58 U29.AG7 U29.AG49 U29.AG51 U29.AG53 U29.AG59 U29.AH2 U29.AH6 U29.AH8 U29.AH15 U29.AH17 U29.AH23 U29.AH29 U29.AH40 U29.AH42 U29.AH46 U29.AH52 U29.AH54 U29.AH56 U29.AH58 U29.AK1 U29.AK5 U29.AK11 U29.AK16 U29.AK18 U29.AK24 U29.AK28 U29.AK33 U29.AK41 U29.AK43 U29.AK53 U29.AK59 U29.AM6 U29.AM12 U29.AM17 U29.AM23 U29.AM27 U29.AM34 U29.AM38 U29.AM40 U29.AM42 U29.AM44 U29.AM46 U29.AM52 U29.AM54 U29.AM56 U29.AM58 U29.AN49 U29.AN51 U29.AN53 U29.AN59 U29.AP6 U29.AP8 U29.AP14 U29.AP24 U29.AP28 U29.AP37 U29.AP39 U29.AP41 U29.AP54 U29.AP58 U29.AR1 U29.AR5 U29.AR9 U29.AR11 U29.AT6 U29.AT10 U29.AT12 U29.AT15 U29.AT25 U29.AT29 U29.AT40 U29.AT42 U29.AT52 U29.AT54 U29.AT56 U29.AU1 U29.AU7 U29.AU9 U29.AU16 U29.AU18 U29.AU24 U29.AU31 U29.AU33 U29.AU35 U29.AU37 U29.AU39 U29.AU41 U29.AU43 U29.AU45 U29.AU49 U29.AU53 U29.AV8 U29.AV12 U29.AV52 U29.AV58 U29.AW5 U29.AW7 U29.AW9 U29.AW11 U29.AW17 U29.AW23 U29.AW42 U29.AW46 U29.AY6 U29.AY8 U29.AY12 U29.AY56 U29.B2 U29.B4 U29.B6 U29.B20 U29.B32 U29.B44 U29.B48 U29.B52 U29.B58 U29.BA1 U29.BA7 U29.BA14 U29.BA16 U29.BA18 U29.BA24 U29.BA26 U29.BA31 U29.BA33 U29.BA37 U29.BA43 U29.BA49 U29.BA53 U29.BB6 U29.BB10 U29.BB12 U29.BB17 U29.BB23 U29.BB27 U29.BB29 U29.BB34 U29.BB36 U29.BB42 U29.BB46 U29.BB52 U29.BB54 U29.BB58 U29.BC5 U29.BC7 U29.BC9 U29.BC49 U29.BC51 U29.BC53 U29.BC59 U29.BD6 U29.BD8 U29.BD12 U29.BD16 U29.BD18 U29.BD41 U29.BD43 U29.BD45 U29.BD56 U29.BE1 U29.BE7 U29.BE11 U29.BE57 U29.BE59 U29.BF6 U29.BF12 U29.BF15 U29.BF17 U29.BF19 U29.BF21 U29.BF23 U29.BF25 U29.BF27 U29.BF29 U29.BF34 U29.BF38 U29.BF40 U29.BF42 U29.BF44 U29.BF46 U29.BF52 U29.BF58 U29.BG5 U29.BG7 U29.BG49 U29.BG53 U29.BH6 U29.BH8 U29.BH12 U29.BH20 U29.BH32 U29.BH38 U29.BH40 U29.BH42 U29.BH52 U29.BH56 U29.BH58 U29.BJ1 U29.BJ7 U29.BJ11 U29.BJ13 U29.BJ15 U29.BJ17 U29.BJ23 U29.BJ27 U29.BJ35 U29.BJ39 U29.BJ41 U29.BJ45 U29.BK6 U29.BK20 U29.BK48 U29.BK50 U29.BK54 U29.BK58 U29.BL3 U29.BL5 U29.BL7 U29.BL13 U29.BL23 U29.BL30 U29.BL41 U29.BM2 U29.BM6 U29.BM8 U29.BM10 U29.BM16 U29.BM18 U29.BM22 U29.BM26 U29.BM28 U29.BM34 U29.BM36 U29.BM40 U29.BM44 U29.BM46 U29.BM56 U29.BN13 U29.BN17 U29.BN21 U29.BN23 U29.BN27 U29.BN30 U29.BN35 U29.BN39 U29.BN41 U29.BN45 U29.BN53 U29.BP2 U29.BP6 U29.BP10 U29.BP18 U29.BP26 U29.BP32 U29.BP40 U29.BP48 U29.BP58 U29.BR1 U29.BR5 U29.BR41 U29.BR53 U29.BR59 U29.BT2 U29.BT8 U29.BT12 U29.BT16 U29.BT20 U29.BT24 U29.BT28 U29.BT34 U29.BT38 U29.BT42 U29.BT46 U29.BT50 U29.BT54 U29.BT56 U29.BU1 U29.BU3 U29.BU41 U29.BU59 U29.BV2 U29.BV6 U29.BV8 U29.BV12 U29.BV16 U29.BV20 U29.BV24 U29.BV28 U29.BV34 U29.BV44 U29.BV48 U29.BV52 U29.BV58 U29.BW3 U29.BW5 U29.BW7 U29.BW15 U29.BW19 U29.BW25 U29.BW30 U29.BW37 U29.BW45 U29.BW47 U29.BW49 U29.BW51 U29.BW53 U29.BW55 U29.BW57 U29.C1 U29.C35 U29.C41 U29.C59 U29.D8 U29.D12 U29.D16 U29.D20 U29.D24 U29.D28 U29.D34 U29.D38 U29.D42 U29.D46 U29.D50 U29.D54 U29.D56 U29.E1 U29.E41 U29.E53 U29.E59 U29.F2 U29.F6 U29.F8 U29.F10 U29.F18 U29.F32 U29.F36 U29.F40 U29.F48 U29.F58 U29.G5 U29.G13 U29.G17 U29.G21 U29.G23 U29.G27 U29.G30 U29.G35 U29.G39 U29.G41 U29.G45 U29.G53 U29.H10 U29.H16 U29.H18 U29.H22 U29.H28 U29.H34 U29.H36 U29.H40 U29.H44 U29.H46 U29.H56 U29.J13 U29.J30 U29.J41 U29.K6 U29.K10 U29.K24 U29.K48 U29.K50 U29.K54 U29.K58 U29.L1 U29.L5 U29.L7 U29.L11 U29.L13 U29.L15 U29.L17 U29.L19 U29.L21 U29.L23 U29.L33 U29.L35 U29.L37 U29.L39 U29.L41 U29.L45 U29.M6 U29.M12 U29.M16 U29.M18 U29.M24 U29.M32 U29.M38 U29.M42 U29.M52 U29.M56 U29.M58 U29.N7 U29.N49 U29.N53 U29.P6 U29.P8 U29.P12 U29.P25 U29.P34 U29.P36 U29.P38 U29.P40 U29.P46 U29.P52 U29.P58 U29.R5 U29.R7 U29.R9 U29.R11 U29.R57 U29.R59 U29.T16 U29.T20 U29.T22 U29.T24 U29.T26 U29.T28 U29.T41 U29.T43 U29.T45 U29.T56 U29.U1 U29.U7 U29.U11 U29.U49 U29.U51 U29.U53 U29.U59 U29.V2 U29.V6 U29.V15 U29.V17 U29.V19 U29.V27 U29.V34 U29.V38 U29.V42 U29.V44 U29.V46 U29.V52 U29.V54 U29.V58 U29.W14 U29.W16 U29.W18 U29.W26 U29.W28 U29.W33 U29.W41 U29.W43 U29.W45 U29.W49 U29.W53 U29.Y2 U29.Y6 U29.Y8 U29.Y10 U29.Y12 U29.Y56 U30.4 U31.1 U32.8 U32.9 U32.10 U32.11 U32.12 U32.13 U33.1 U34.49 U35.7 U35.10 U35.11 U36.A1 U36.A4 U36.A9 U36.A10 U36.B2 U36.B5 U36.B8 U36.C5 U36.C6 U36.C9 U36.C10 U36.D4 U36.D8 U36.E1 U36.E5 U36.E9 U36.E10 U36.F9 U36.F10 U36.G6 U36.G8 U36.G10 U36.H5 U36.H7 U36.H10 U36.J1 U36.J4 U36.J5 U36.J6 U36.J8 U36.J9 U36.J10 U36.K1 U36.K2 U36.K3 U36.K5 U36.K6 U36.K8 U36.K9 U36.K10 U36.L1 U36.L2 U36.L3 U36.L4 U36.L5 U36.L6 U36.L8 U36.L9 U36.L10 U36.M1 U36.M2 U36.M3 U36.M4 U36.M5 U36.M6 U36.M8 U36.M9 U36.M10 U36.N2 U36.N3 U36.N4 U36.N5 U36.N6 U36.N8 U36.N9 U37.1 Y1.2 Y1.4 Y2.2 Y4.2 Y4.4
V1.0S_EN: PR66.2 PU5.M11 U7.9
V1.0S_SENSE: PR58.1 PU5.L12
V1.0SX_EN: PR77.2 PU5.N11 U7.2
V1.0SX_SENSE: PR60.1 PU5.K12
V3.3S_EN_B: PQ11.4 PU5.H12
VCC_FG: PC30.2 PR32.1 PU1.D1 TP23.1
VCCA_PWROK: PU5.J5 U29.AK55
VDD1P2_GRF: C214.2 L7.1 U22.E2 U22.E5
VDD_1V8_AUDIO: R162.2 R353.2 R354.1 R369.1 R381.1 R383.1
VDD_1V8_MIC1: C147.2 C152.2 L5.1 R212.1 U2.6
VDDCORE: C197.2 U22.C1 U22.D1
VDDI_DSC: C225.2 U26.K2
VIN_LDO: C363.1 C364.2 L27.2 U36.C1
3G_ON: PQ5.2 PR47.1 U12.G2
24190_SCL: PR117.1 PU7.5
24190_SDA: PR118.1 PU7.6
24192_BTST: PC121.2 PU7.21
24192_OTG: PR123.2 PR124.1 PR137.1 PU7.8
24192_PMID: PC118.2 PU7.23
24192_SW: PC121.1 PL20.1 PU7.19 PU7.20
63020_EN: PC133.2 PR100.2 PR133.2 PR134.1 PU8.6 Q24.5 R87.2
63020_FB: PC134.1 PR132.1 PR136.2 PU8.10
63020_FB_S: PC134.2 PR136.1 PR143.1
63020_L1: PL19.2 PU8.4
63020_L2: PL19.1 PU8.2
63020_PS: PR135.2 PR144.2 PU8.7
63020_VINA: PC135.1 PR142.2 PU8.8
+V_CH_REGN: PC119.2 PR140.2 PR141.2 PU7.22
+V_SFR0: C28.1 C42.2 C260.1 R82.2 U29.BV36 U29.BW35 U29.M40
+V_SFR1: C23.1 C44.1 C53.1 C76.2 C287.1 R81.2 U29.AE1 U29.AH27 U29.AP16 U29.P44
+V_VCC: C34.2 C36.1 C38.1 C39.2 C40.1 C266.1 C268.1 C270.1 PC54.1 PC57.1 PC60.1 PC78.1 PL1.2 PL2.2 PL7.2 PL9.2 PL11.2 PR74.2 U29.A17 U29.A19 U29.A21 U29.A23 U29.A25 U29.AA32 U29.AA34 U29.AA36 U29.AC33 U29.AC35 U29.AF33 U29.AF35 U29.AH32 U29.AH34 U29.AH36 U29.AK31 U29.AK35 U29.AK37 U29.AM29 U29.AM32 U29.AM36 U29.AP31 U29.AP33 U29.AP35 U29.AT32 U29.AT34 U29.B18 U29.B22 U29.B26 U29.C25 U29.D26 U29.E25 U29.F26 U29.G25 U29.H26 U29.J25 U29.K26 U29.L25 U29.L27 U29.L30 U29.M26 U29.M28 U29.P29 U29.P32 U29.T31 U29.T33 U29.T35 U29.T37 U29.V29 U29.V32 U29.V36 U29.W31 U29.W35 U29.W37
+V_VCC_SENSE: PR67.2 U29.AT38
+V_VNN: C29.2 C33.2 C37.1 C46.1 C49.2 C51.2 C52.2 C54.2 PC55.1 PC56.1 PC66.1 PC72.1 PL3.1 PL4.1 PL5.1 PL8.1 PL10.1 PR76.2 U29.AA19 U29.AA21 U29.AA25 U29.AC20 U29.AC22 U29.AC26 U29.AD19 U29.AD21 U29.AD25 U29.AD27 U29.AD29 U29.AD32 U29.AD34 U29.AF20 U29.AF22 U29.AF26 U29.AH19 U29.AH21 U29.AH25 U29.AK20 U29.AK22 U29.AK26 U29.AM19 U29.AM21 U29.AM25 U29.AP20 U29.AP22 U29.AP26 U29.AT23 U29.AT27 U29.AU20 U29.AU22 U29.AU26 U29.AU28 U29.AW19 U29.AW21 U29.AW25 U29.AW27 U29.AW29 U29.AW32 U29.AW34 U29.AW36 U29.AW38 U29.AW40 U29.BA20 U29.BA28 U29.BA35 U29.BA39 U29.BA41 U29.BB19 U29.BB21 U29.BB25 U29.BB32 U29.BB38 U29.BB40 U29.BD20 U29.BD22 U29.BD24 U29.BD26 U29.BD28 U29.BD31 U29.BD33 U29.BD35 U29.BD37 U29.BD39 U29.BK2 U29.BL1 U29.BN1 U29.BV10 U29.BV14 U29.BW9 U29.BW11 U29.BW13 U29.V21 U29.V23 U29.V25 U29.W20 U29.W22 U29.W24
+V_VNN_SENSE: PR69.1 U29.BA22
+V_VSS_SENSE: PR68.2 U29.AT36
+VBL_LCM: C41.1 C45.1 CN9.9 CN9.10 PC49.2 PC50.2 PC51.2 PC52.2 PD2.1 PR87.2
+VCLK_SFR0: C60.1 R70.2 U29.AM15
+VCLK_SFR1: C68.1 R71.2 U29.AP12
+VHDMI: D5.2 D6.2 F1.3 PC24.1 PU5.M13
+VLPC: C271.1 R304.2 U29.BV18 U29.BW17
+VREF_CA0: C180.2 C216.2 R238.1 R239.2 U23.A10 U23.J1
+VREF_CA1: C183.2 C210.2 R240.2 R241.1 U24.A10 U24.J1
+VREF_DQ0: C12.2 C206.2 PC1.1 PU5.B6 R19.1 R22.2 U23.H17 U23.U8
+VREF_DQ1: C15.2 C207.2 PC2.1 PU5.C6 R20.1 R23.2 U24.H17 U24.U8
+VREFB: PC13.1 PR7.2 PU5.M8
+VREFT: PC8.1 PR54.1 PR107.1 PR114.1 PU5.N7
+VRTC: C50.1 R42.2 R111.1 R113.2 R324.1 R325.1
+VRTC_SOC: R42.1 U29.M22
+VSDIO: PC4.1 PU5.G2 R301.2
+VSDIO_SOC: C267.1 R301.1 U29.BW23
+VSPI: C78.2 C92.2 C276.2 R72.2 R79.2 R83.2 R313.2 U5.B2 U8.C2 U30.8
+VSPI_PROG: C80.2 R85.2 R91.2 U5.C2
+VSYS: PC61.1 PC62.1 PC63.1 PC64.1 PC65.1 PC67.1 PC68.1 PC69.1 PC75.1 PC76.1 PC79.1 PC81.2 PC85.1 PC87.1 PC88.1 PC92.1 PC93.2 PC96.1 PC104.2 PC126.2 PC131.2 PL16.2 PL20.2 PQ4.1 PQ4.2 PQ4.3 PQ6.1 PQ6.2 PQ6.3 PR8.1 PR18.2 PR19.2 PR27.1 PR28.2 PR39.1 PR49.1 PR79.1 PR119.2 PU5.A4 PU5.A9 PU5.A11 PU5.B5 PU5.B11 PU5.D1 PU5.E2 PU5.E15 PU5.H2 PU5.H3 PU5.K13 PU5.K14 PU5.K15 PU5.L2 PU5.M1 PU5.P5 PU5.P11 PU5.R4 PU5.R8 PU5.R10 PU5.R11 PU7.15 PU7.16 R185.1 R329.2 R672.2
+VSYS_S: PC21.1 PU5.J12
+VSYS_V3.3A: PC122.1 PC125.1 PC127.2 PR119.1 PR133.1 PR142.1 PR144.1 PU8.5
+VUSBPHY: PC22.1 PU5.H13
+XDP_VSPI_PROG: CN1.39 R85.1
AC_PRESENT: PR85.2 U29.E21
AC_PRESENT_R: PR85.1 PU5.H5
ACCEL_C1: C360.1 U35.6
ACCEL_INT1: U10.18 U35.5
ACCEL_INT2: U10.19 U35.4
ACCEL_L: R154.2 R156.1 U10.11
ACCEL_M: R153.1 R155.2 U10.12
ACCEL_N: R146.2 R147.1 U10.13
ACCEL_SETN: C359.1 U35.13
ACCEL_SETP: C359.2 U35.12
ACPI_INT#: R166.2 U12.A3 U29.F20
ADCDAT: C323.2 R368.2 U34.32
ALS_INT#: R3.2 U1.3 U10.28
ANT1_PAD1: C142.2 R210.2 R211.1
ANT1_R: R211.2 U19.4
ANT2_PAD2: C140.2 R205.2 R209.1
ANT2_R: R209.2 U20.4
ANT_0: C373.2 L28.1 U36.N10
ANT_1: C374.2 L29.1 U36.N1
AUDIO_SCL: R358.1 U34.38
AUDIO_SDA: R357.1 U34.39
BAT-: CN10.7 CN10.8 PR130.2 SS2.2
BAT_CLK: C117.1 PR31.2 PR117.2 R171.1 U12.B8
BAT_DATA: C111.1 PR33.2 PR118.2 R167.1 U12.C8
BAT_ID: CN10.6 PC11.1 PR6.2 PR7.1 PU5.M7 U12.A1
BAT_SCL: PR31.1 PU1.A3 TP22.1
BAT_SDA: PR33.1 PU1.B3 TP25.1
BATLED0#: R6.1 U12.F9
BATLED1#: R4.1 U12.H9
BATT1_THERM: PR128.2 PR141.1 PU7.12
BATT2_THERM: PR127.2 PR140.1 PU7.11
BATT_THERM: PR25.1 U12.D1
BATT_THERM_S: CN10.5 PR25.2 PR37.2
BCLK: C328.2 R374.2 U34.30
BOARD_ID_0: PU5.J11 R123.2 R136.1
BOARD_ID_1: PU5.J10 R121.2 R134.1
BOARD_ID_2: PU5.J9 R122.2 R135.1
BOARD_ID_3: PU5.F8 R126.2 R139.1
BODYSAR_N: R177.1 R271.1 U12.E1
BODYSAR_S: R175.1 U12.C9 U29.BN37
BOOT0: R143.1 U10.44
BQ27520_A1: PC28.1 PC31.1 PR23.2 PU1.A1 TP16.1
BQ27520_B1: PC29.2 PC31.2 PR24.2 PU1.B1 TP17.1
BQ27520_D2: PR26.1 PR27.2 PU1.D2 TP14.1
BQ27520_D3: PC35.1 PR35.2 PU1.D3 TP28.1
BQ27520_E1: PC32.1 PR28.1 PU1.E1 TP18.1
BQ27520_E3: PC34.1 PR32.2 PR36.2 PU1.E3 TP26.1
BRTC_EXTPAD: C274.2 U29.E9
BT_DEV_EN: R334.2 U29.BM14 U36.C3
BT_DEV_WAKE: R395.1 U29.BL15
BT_FM_PCM_I2S_CLK_R: R397.1 U36.F5
BT_FM_PCM_I2S_IN_R: R399.1 U36.G5
BT_FM_PCM_I2S_OUT_R: R398.1 U36.F4
BT_FM_PCM_I2S_SYNC_R: R401.1 U36.G4
BT_HOST_WAKE: R302.1 U29.J23 U36.B7
CAM1_CSI_A_D0N: CN6.2 U17.5
CAM1_CSI_A_D0P: CN6.20 U17.4
CAM1_CSI_A_D1N: CN6.5 U21.5
CAM1_CSI_A_D1P: CN6.17 U21.4
CAM1_CSI_CLKN: CN6.19 U15.5
CAM1_CSI_CLKP: CN6.4 U15.4
CAM1_PWDN: Q16.1 R224.1 R229.2 U29.D40
CAM1_PWDN_C: CN6.6 R213.1
CAM1_PWDN_R: Q14.5 Q16.3 R213.2 R214.1 R223.2 R229.1
CAM2_CSI_CLKN: CN5.14 U16.5
CAM2_CSI_CLKP: CN5.8 U16.4
CAM2_CSI_D0N: CN5.10 U18.5
CAM2_CSI_D0P: CN5.13 U18.4
CAM2_PWDN: Q15.1 R221.2 R227.1 U29.G37
CAM2_PWDN_C: CN5.6 Q15.3 R220.2 R221.1
CAM_FLHD: TP48.1 U29.F38
CAM_I2C_SCL_2M: CN5.17 R201.1
CAM_I2C_SCL_5M: CN6.16 R204.1
CAM_I2C_SDA_2M: CN5.5 R200.2
CAM_I2C_SDA_5M: CN6.7 R203.2
CAMERA_1_RESET#: Q13.1 R214.2 U29.E39
CAMERA_2_RESET#: CN5.18 Q12.1 U29.K38
CAMERA_3_RESET#: TP50.1 U29.H38
CBUCK_OUT: L27.1 U36.B1
CH_DISABLE: PR138.2 U12.H3
CH_DISABLE_C: PR125.2 PR138.1 PR139.1 PU7.9
CH_INT: PR122.2 R33.2 U12.J3
CH_INT_C: PR122.1 PR129.1 PU7.7
CH_OTG: PR137.2 U12.A6
CHG_AGND: PC119.1 PR22.1 PR123.1 PR125.1 PR126.2 PR127.1 PR128.1
CHG_STAT: PR116.1 PU7.4 U12.J2
CHG_USBDN: PU7.3 R668.2 U11.6
CHG_USBDP: PU7.2 R668.1 U11.7
CLK_USB_REF_DN: R318.1 U29.G7
CLK_USB_REF_DP: R317.1 U29.H6
CODEC_RESET#: PU5.L10 R162.1 R163.2
CORE_PWROK: PU5.K4 R89.2 U29.G9
CPU_VREF: C19.2 R21.1 R24.2 U29.AK57
CPVDD: C343.2 C347.1 R383.2 U34.23
CPVEE: C345.1 U34.27
CPVPP: C344.1 U34.24
DACDAT: C325.2 R371.2 U34.31
DACREF: C332.2 C333.1 L16.2 U34.10
DB_ANT_B: C373.1 CN14.1 L30.1
DB_ANT_C: C374.1 CN15.1 L31.1
DBG_RESETBTN#: CN1.24 U29.BN7
DBVDD: C311.1 C316.2 R354.2 U34.43
DCIN_5V_IN: CN13.1 CN13.2 CN13.3 CN13.4 CN13.5 PL21.1 PL22.1
DCVDD: C306.1 C312.2 R361.2
DCVDD_C: R361.1 U34.42
DDI0_DDC_SCL: Q8.1 R119.1 U29.D32
DDI0_DDC_SDA: Q7.1 R117.1 U29.H32
DDI0_HPD#: Q4.3 R93.1 U29.K32
DDI0_RCOMP_DN: R60.1 U29.BB8
DDI0_RCOMP_DP: R60.2 U29.BA9
DDI0_TX0_DN: C84.2 U29.BE9
DDI0_TX0_DP: C83.2 U29.BF8
DDI0_TX1_DN: C86.2 U29.BD4
DDI0_TX1_DP: C85.2 U29.BE3
DDI0_TX2_DN: C90.2 U29.BE5
DDI0_TX2_DP: C89.2 U29.BF4
DDI0_TX3_DN: C93.2 U29.BB4
DDI0_TX3_DP: C91.2 U29.BA5
DDR3_RCOMP0: R30.1 U29.AH50
DDR3_RCOMP1: R32.1 U29.AK51
DDR3_RCOMP2: R31.1 U29.AH48
DDR3_REF_N: R286.2 U29.AM50
DDR3_REF_P: R285.2 U29.AM48
DEBUG_CS: PU5.R2 R112.2 TP5.1
DEBUG_I2C_CLK: PR109.2 PU5.R1
DEBUG_I2C_DATA: PR110.2 PU5.P1
DEBUG_SVID_ALERT_B: PR64.2 PU5.A2 TP61.1
DEBUG_SVID_CLK: PR65.2 PU5.A1 TP60.1
DEBUG_SVID_DATA: PR63.2 PU5.B1 TP59.1
DMIC1_DAT: C318.1 R376.1 T17.1 U2.5
DMIC_SCL: C304.1 R356.2 T16.1 U2.4
DMIC_SCL_R: R356.1 U34.41
DRAM_PWROK: PU5.K3 U29.AK49
E775AGND: C122.2 C124.2 R176.1 U12.B2
EDP_BKLT_EN: PR2.2 PR94.2 PU6.1
EMMC_CLK: C6.1 U26.W6 U29.BP20
EMMC_CMD: R14.2 U26.W5 U29.BU21
EMMC_DATA_0: TP2.1 U26.H3 U29.BJ21
EMMC_DATA_1: U26.H4 U29.BM20
EMMC_DATA_2: U26.H5 U29.BR21
EMMC_DATA_3: U26.J2 U29.BR19
EMMC_DATA_4: U26.J3 U29.BK22
EMMC_DATA_5: U26.J4 U29.BU19
EMMC_DATA_6: U26.J5 U29.BJ19
EMMC_DATA_7: U26.J6 U29.BL21
EMMC_RCOMP: R44.2 U29.BH24
EMMC_RESET: R15.2 U26.U5 U29.BH22
FB1: CN9.14 PU6.11
FB2: CN9.13 PU6.10
FB3: CN9.12 PU6.9
FG_BATT_GD#: PR29.2 U12.B6
FG_BATT_GD#_R: PR29.1 PU1.B2 TP15.1
FG_BATT_INTN: PR30.2 PU1.A2 TP21.1 U12.J1
FG_BATT_LOW: PU1.C3 TP24.1 U12.H2
FLASH_TORCH: TP47.1 U29.B38
FLASH_TRIG: TP49.1 U29.C39
FRONT_CAM_LED: TP45.1 U29.J39
GPIO0VDD: PC25.1 PR20.1 PU5.J13
GPIO_RCOMP18: R67.1 U29.E13
GPIO_SOC_V1P0SX_S: Q5.1 U29.BN15
GPIO_SOC_V1P0SX_S_5P0: Q5.3 R101.2 U7.1
GPIO_SUS1: U3.A1 U29.K14
GPIO_SUS2: R33.1 U3.B1 U29.C17
GPIO_SUS3: R34.2 U3.C1 U29.E19
GPIO_SUS4: R35.2 U3.D1 U29.D18
GPS_ANT: C253.1 C254.2 CN8.1
GPS_BLANK: R237.2 U22.A3
GPS_CAL: R242.2 U22.A5
GPS_CLK_32K_R: R261.1 U22.A6
GPS_DISABLE#: CN7.26 TP43.1
GPS_EXT_LN_OUT: U25.1 U27.6
GPS_EXT_LNA_IN: L9.2 U27.3
GPS_HOSTREQ: TP57.1 U29.BK14
GPS_LNA_EN: U22.B6 U27.5
GPS_REFCAP: C191.1 U22.C2
GPS_RFIP: L6.2 U22.D6
GPS_SAW1_IN: C252.2 C253.2 U28.1
GPS_SAW1_OUT: C229.1 U28.4
GPS_SAW1_OUT1: C229.2 L9.1
GPS_SAW2_OUT: L6.1 U25.4
GPS_SYNC: R253.1 U22.B5
GPS_TCXO_OUT: U22.E4 Y2.3
GPS_UART_CTS#_R: R266.2 U22.B1
GPS_UART_RTS#_R: R256.2 U22.B2
GPS_UART_RXD_R: R259.2 U22.A2
GPS_UART_TXD_R: R258.2 U22.A1
GPS_WAKEUP: R260.1 U22.B3 U29.BH14
GYRO_CS: R350.2 U32.5
GYRO_INT1: U10.20 U32.7
GYRO_INT2: U10.39 U32.6
GYRO_L: R144.1 R145.2 U10.14
GYRO_M: R133.2 R142.1 U10.15
GYRO_N: R129.1 R130.2 U10.16
GYRO_SA0: R348.2 R349.2 U32.4
HDA_RCOMP: R36.1 U29.BH28
HDMI_DDC_SCL_AP_J: CN3.17 Q8.3 R120.1 T4.1
HDMI_DDC_SDA_AP_J: CN3.18 Q7.3 R118.1 T5.1
HDMI_TXCN_R: C93.1 C756.2 CN3.14 R109.2 R110.2
HDMI_TXCP_R: C91.1 C466.2 CN3.12 R108.2 R109.1
HDMI_TXD0N_R: C90.1 C458.2 CN3.11 R106.2 R107.2
HDMI_TXD0P_R: C89.1 C452.2 CN3.9 R105.2 R106.1
HDMI_TXD1N_R: C86.1 C447.2 CN3.8 R103.2 R104.2
HDMI_TXD1P_R: C85.1 C437.2 CN3.6 R102.2 R103.1
HDMI_TXD2N_R: C84.1 C378.2 CN3.5 R99.2 R100.2
HDMI_TXD2P_R: C83.1 C377.2 CN3.3 R98.2 R99.1
HDMI_VL: Q6.3 R98.1 R100.1 R102.1 R104.1 R105.1 R107.1 R108.1 R110.1
HEAD_DET#_CODEC: R375.1 U34.8
HEAD_DET#_R: C326.2 D9.1 R369.2 R375.2 R378.2
HEADSET_MIC: CN13.20 R384.1 R385.1
HOLD#_FLASH: R79.1 U30.7
HOME_SCREEN: CN13.8 PU5.E7 Q18.5 R670.1
HOME_SCREEN_L: Q18.2 Q18.3 R410.2
HOME_SCREEN_S: Q18.6 R337.2 U29.BL11
HP_AGND: CN13.16 CN13.19 R388.2
HP_DET: CN13.14 R378.1
HP_DET_J: C81.1 CN3.1 Q4.1 R94.1 T3.2
HP_L1: C334.2 L18.1 U34.28
HP_MIC: C329.1 C355.2 R385.2
HP_MIC_BIAS: C327.1 C354.1 R372.1 R384.2
HP_OUT_L: C336.2 C337.1 CN13.18 L18.2
HP_OUT_R: C346.2 C349.1 CN13.17 L20.2
HP_R1: C339.2 L20.1 U34.26
HPGND: R382.2 R388.1 U34.25
I2C_0_SCL: R168.1 U12.B9 U29.BK32
I2C_0_SDA: R170.1 U12.A9 U29.BJ30
I2C_2MP_CAM_SCL: R201.2 U29.BH34
I2C_2MP_CAM_SDA: R200.1 U29.BN33
I2C_4_SCL: R340.1 U29.BU33 U31.3
I2C_4_SDA: R342.1 U29.BU30 U31.4
I2C_5_SCL: R359.1 U29.BP34 U33.3
I2C_5_SCL_C: CN11.5 R366.1 U33.6
I2C_5_SDA: R362.1 U29.BT32 U33.4
I2C_5_SDA_C: CN11.4 R370.1 U33.5
I2C_5MP_CAM_SCL: R204.2 U29.BJ33
I2C_5MP_CAM_SDA: R203.1 U29.BM32
I2C_7_SCL: CN1.28 U29.BR39
I2C_7_SDA: CN1.29 U29.BK40
I2C_ACCEL_SCL: R389.2 U35.2
I2C_ACCEL_SDA: R387.2 U35.3
I2C_CODEC_SCL: R358.2 U29.BL33
I2C_CODEC_SDA: R357.2 U29.BR30
I2C_GYRO_SCL: R346.2 U32.2
I2C_GYRO_SDA: R347.2 U32.3
I2C_PMIC_SCL: PR112.2 PU5.M5 U29.BK34
I2C_PMIC_SDA: PR111.2 PU5.M6 U29.BR33
I2C_SENSOR_SCL: R8.2 R346.1 R389.1 RP1.3 U10.42
I2C_SENSOR_SDA: R2.1 R347.1 R387.1 RP1.1 U10.43
I2C_SENSORHUB_SCL: R341.1 U10.21 U31.6
I2C_SENSORHUB_SDA: R343.1 U10.22 U31.5
I2C_VIO: PR1.2 PU5.M4
I2CM_CLK: PU5.N4 TP7.1
I2CM_DATA: PU5.N5 TP8.1
I2CM_SZ: PR8.2 PU5.P9
I2S_0_CLK: C313.1 R374.1 U29.BR27
I2S_0_FS: R377.1 U29.BP28
I2S_0_RXD: R368.1 U29.BL27
I2S_0_TXD: R371.1 U29.BU27
I2S_1_CLK: C370.1 R397.2 U29.BT26
I2S_1_FS: R401.2 U29.BK28
I2S_1_RXD: R399.2 U29.BK16
I2S_1_TXD: R398.2 U29.BR25
I2S_2_CLK: C307.1 R352.1 U29.BL37
I2S_2_CODEC_CLK: C310.2 R352.2 U34.36
I2S_2_CODEC_FS: C315.2 R360.2 U34.35
I2S_2_CODEC_RXD: C317.2 R363.2 U34.34
I2S_2_CODEC_TXD: C320.2 R365.2 U34.33
I2S_2_FS: R293.2 R296.2 R360.1 U29.BT36
I2S_2_RXD: R363.1 U29.BP36
I2S_2_TXD: R289.2 R290.2 R365.1 R411.2 U29.BK36
I2S_IRQ#: R35.1 R174.2 U3.D5
ICLK_ICOMP: R66.2 U29.AK14
ICLK_RCOMP: R65.2 U29.AH12
ILIMIT: PR126.1 PU7.10
IN1P: R376.2 U34.5
IN2P: C329.2 U34.7
JTAG2_TCK: CN1.3 R28.2 U3.B3
JTAG2_TDI: CN1.1 R27.2 U3.A4
JTAG2_TDO: CN1.2 U3.B5
JTAG2_TMS: CN1.4 R29.2 U3.A2
JTAG_SENSOR_SWCLK: CN1.17 U10.37
JTAG_SENSOR_SWDIO: CN1.18 U10.34
LCD_RST#_SOC: CN9.2 R80.2 R294.1
LCD_SHLR: CN9.5 TP55.1
LCD_UPDN: CN9.8 TP54.1
LCM_DDC_SCL: CN9.16 Q3.3 R58.2 R673.2
LCM_DDC_SDA: CN9.15 Q2.3 R57.2 R674.2
LID2#: D8.2 HE1.2 R161.2 U12.H1
LIGHT_SCL: R8.1 U1.5
LIGHT_SDA: R2.2 U1.2
LPC_AD0: CN1.7 CN2.5 U29.BK18
LPC_AD1: CN1.8 CN2.4 U29.BL19
LPC_AD2: CN1.9 CN2.3 U29.BR15
LPC_AD3: CN1.10 CN2.2 U29.BP16
LPC_CLKOUT_1: C70.1 C82.1 CN1.12 CN2.6 U29.BL17
LPC_CLKRUN#: CN1.13 U29.BU17
LPC_FRAME#: CN1.11 CN2.1 U29.BT18
LPC_RCOMP: R49.2 U29.BH18
LPC_SERIRQ: CN1.14 U29.BR11
LRCK: C331.2 R377.2 U34.29
M0_A_ZQ0: R231.2 U23.B11
M0_A_ZQ1: R232.2 U23.C11
M0_B_ZQ0: R279.2 U23.E2
M0_B_ZQ1: R276.2 U23.E3
M1_A_ZQ0: R281.2 U24.B11
M1_A_ZQ1: R283.2 U24.C11
M1_B_ZQ0: R233.2 U24.E2
M1_B_ZQ1: R234.2 U24.E3
M_0_CA0: R267.2 U23.B5 U23.L2 U29.M50
M_0_CA1: R269.2 U23.C5 U23.L3 U29.N51
M_0_CA2: R272.2 U23.D5 U23.L4 U29.L51
M_0_CA3: R254.2 U23.B6 U23.K2 U29.L55
M_0_CA4: R264.2 U23.C6 U23.K3 U29.R49
M_0_CA5: R251.2 U23.C9 U23.G3 U29.R51
M_0_CA6: R243.2 U23.D9 U23.G4 U29.P50
M_0_CA7: R244.2 U23.B10 U23.F2 U29.L57
M_0_CA8: R245.2 U23.C10 U23.F3 U29.P48
M_0_CA9: R246.2 U23.D10 U23.F4 U29.T52
M_0_CKE0: U23.C7 U29.H58
M_0_CKE1: U23.J3 U29.C57
M_0_CKE2: U23.D7 U29.K56
M_0_CKE3: U23.J4 U29.D58
M_0_CLKN0: R11.2 U23.C8 U29.N57
M_0_CLKN2: R12.2 U23.H2 U29.P56
M_0_CLKP0: R11.1 U23.B8 U29.N55
M_0_CLKP2: R12.1 U23.H3 U29.P54
M_0_CS0#: U23.D6 U23.K4 U29.J57
M_0_CS2#: U23.B7 U23.J2 U29.B56
M_0_DM0: U23.N6 U29.M44
M_0_DM1: U23.P4 U29.E45
M_0_DM2: U23.P11 U29.E51
M_0_DM3: U23.P8 U29.J51
M_0_DM4: U23.L14 U29.Y52
M_0_DM5: U23.H14 U29.W57
M_0_DM6: U23.D14 U29.AE55
M_0_DM7: U23.F13 U29.AE53
M_0_DQ0: U23.N4 U29.H42
M_0_DQ1: U23.T5 U29.M46
M_0_DQ2: U23.R5 U29.J47
M_0_DQ3: U23.P5 U29.L43
M_0_DQ4: U23.N5 U29.K42
M_0_DQ5: U23.T6 U29.K46
M_0_DQ6: U23.R6 U29.J45
M_0_DQ7: U23.P6 U29.G43
M_0_DQ8: U23.P2 U29.B42
M_0_DQ9: U23.N3 U29.C47
M_0_DQ10: U23.T2 U29.C43
M_0_DQ11: U23.R3 U29.B46
M_0_DQ12: U23.P3 U29.F46
M_0_DQ13: U23.T3 U29.F44
M_0_DQ14: U23.R2 U29.E43
M_0_DQ15: U23.N2 U29.F42
M_0_DQ16: U23.P13 U29.E49
M_0_DQ17: U23.N11 U29.E47
M_0_DQ18: U23.N12 U29.D48
M_0_DQ19: U23.T14 U29.C53
M_0_DQ20: U23.P12 U29.C49
M_0_DQ21: U23.R14 U29.F52
M_0_DQ22: U23.R13 U29.F50
M_0_DQ23: U23.T13 U29.D52
M_0_DQ24: U23.R11 U29.H52
M_0_DQ25: U23.T10 U29.H48
M_0_DQ26: U23.R9 U29.G47
M_0_DQ27: U23.T9 U29.L47
M_0_DQ28: U23.T11 U29.J49
M_0_DQ29: U23.P10 U29.K52
M_0_DQ30: U23.R10 U29.G49
M_0_DQ31: U23.N10 U29.J53
M_0_DQ32: U23.P15 U29.T50
M_0_DQ33: U23.P16 U29.T48
M_0_DQ34: U23.M14 U29.AA49
M_0_DQ35: U23.N15 U29.V50
M_0_DQ36: U23.N16 U29.V48
M_0_DQ37: U23.L13 U29.AA53
M_0_DQ38: U23.M13 U29.AA51
M_0_DQ39: U23.N14 U29.Y48
M_0_DQ40: U23.K16 U29.U55
M_0_DQ41: U23.L16 U29.U57
M_0_DQ42: U23.K13 U29.R55
M_0_DQ43: U23.L15 U29.T54
M_0_DQ44: U23.K15 U29.Y58
M_0_DQ45: U23.J15 U29.AA55
M_0_DQ46: U23.J16 U29.Y54
M_0_DQ47: U23.K14 U29.T58
M_0_DQ48: U23.C15 U29.AB54
M_0_DQ49: U23.B16 U29.AC57
M_0_DQ50: U23.B13 U29.AG55
M_0_DQ51: U23.C16 U29.AB56
M_0_DQ52: U23.B15 U29.AC55
M_0_DQ53: U23.C14 U29.AA57
M_0_DQ54: U23.C13 U29.AG57
M_0_DQ55: U23.B14 U29.AF56
M_0_DQ56: U23.E14 U29.AF52
M_0_DQ57: U23.F15 U29.AB48
M_0_DQ58: U23.E15 U29.AE49
M_0_DQ59: U23.F14 U29.AF50
M_0_DQ60: U23.F16 U29.AC51
M_0_DQ61: U23.D13 U29.AF48
M_0_DQ62: U23.E16 U29.AD48
M_0_DQ63: U23.E13 U29.AB50
M_0_DQSN0: U23.N7 U29.K44
M_0_DQSN1: U23.R4 U29.C45
M_0_DQSN2: U23.R12 U29.C51
M_0_DQSN3: U23.N9 U29.G51
M_0_DQSN4: U23.M15 U29.Y50
M_0_DQSN5: U23.J13 U29.V56
M_0_DQSN6: U23.D15 U29.AE57
M_0_DQSN7: U23.G13 U29.AD50
M_0_DQSP0: U23.P7 U29.J43
M_0_DQSP1: U23.T4 U29.D44
M_0_DQSP2: U23.T12 U29.B50
M_0_DQSP3: U23.P9 U29.H50
M_0_DQSP4: U23.M16 U29.W51
M_0_DQSP5: U23.J14 U29.W55
M_0_DQSP6: U23.D16 U29.AD58
M_0_DQSP7: U23.G14 U29.AE51
M_0_ODT0: U23.N8 U29.B54
M_0_ODT2: U23.H13 U29.C55
M_1_CA0: R249.2 U24.B5 U24.L2 U29.BH50
M_1_CA1: R248.2 U24.C5 U24.L3 U29.BG51
M_1_CA2: R247.2 U24.D5 U24.L4 U29.BJ51
M_1_CA3: R252.2 U24.B6 U24.K2 U29.BJ55
M_1_CA4: R250.2 U24.C6 U24.K3 U29.BE49
M_1_CA5: R255.2 U24.C9 U24.G3 U29.BE51
M_1_CA6: R265.2 U24.D9 U24.G4 U29.BF50
M_1_CA7: R268.2 U24.B10 U24.F2 U29.BJ57
M_1_CA8: R270.2 U24.C10 U24.F3 U29.BF48
M_1_CA9: R273.2 U24.D10 U24.F4 U29.BD52
M_1_CKE0: U24.J3 U29.BM58
M_1_CKE1: U24.C7 U29.BU57
M_1_CKE2: U24.J4 U29.BK56
M_1_CKE3: U24.D7 U29.BT58
M_1_CLKN0: R10.2 U24.H2 U29.BG55
M_1_CLKN2: R13.2 U24.C8 U29.BF56
M_1_CLKP0: R10.1 U24.H3 U29.BG57
M_1_CLKP2: R13.1 U24.B8 U29.BF54
M_1_CS0#: U24.D6 U24.K4 U29.BL57
M_1_CS2#: U24.B7 U24.J2 U29.BV56
M_1_DM0: U24.H14 U29.BR51
M_1_DM1: U24.D14 U29.BR45
M_1_DM2: U24.F13 U29.BH44
M_1_DM3: U24.L14 U29.BL51
M_1_DM4: U24.P8 U29.AY52
M_1_DM5: U24.P11 U29.BA57
M_1_DM6: U24.N6 U29.AR55
M_1_DM7: U24.P4 U29.AR53
M_1_DQ0: U24.L15 U29.BU53
M_1_DQ1: U24.L16 U29.BP50
M_1_DQ2: U24.K13 U29.BT52
M_1_DQ3: U24.K14 U29.BP52
M_1_DQ4: U24.K15 U29.BR47
M_1_DQ5: U24.K16 U29.BR49
M_1_DQ6: U24.J15 U29.BT48
M_1_DQ7: U24.J16 U29.BU49
M_1_DQ8: U24.B15 U29.BV42
M_1_DQ9: U24.B13 U29.BU47
M_1_DQ10: U24.C15 U29.BU43
M_1_DQ11: U24.C14 U29.BV46
M_1_DQ12: U24.C13 U29.BP46
M_1_DQ13: U24.C16 U29.BP44
M_1_DQ14: U24.B16 U29.BR43
M_1_DQ15: U24.B14 U29.BP42
M_1_DQ16: U24.D13 U29.BK42
M_1_DQ17: U24.E14 U29.BN43
M_1_DQ18: U24.E15 U29.BL45
M_1_DQ19: U24.E16 U29.BH46
M_1_DQ20: U24.F16 U29.BL47
M_1_DQ21: U24.F14 U29.BJ43
M_1_DQ22: U24.E13 U29.BM42
M_1_DQ23: U24.F15 U29.BK46
M_1_DQ24: U24.N16 U29.BM52
M_1_DQ25: U24.N14 U29.BM48
M_1_DQ26: U24.M13 U29.BN47
M_1_DQ27: U24.L13 U29.BJ47
M_1_DQ28: U24.N15 U29.BL49
M_1_DQ29: U24.P16 U29.BK52
M_1_DQ30: U24.M14 U29.BN49
M_1_DQ31: U24.P15 U29.BL53
M_1_DQ32: U24.N10 U29.BD50
M_1_DQ33: U24.P10 U29.BD48
M_1_DQ34: U24.T10 U29.AW49
M_1_DQ35: U24.R10 U29.BB50
M_1_DQ36: U24.R11 U29.BB48
M_1_DQ37: U24.R9 U29.AW53
M_1_DQ38: U24.T9 U29.AW51
M_1_DQ39: U24.T11 U29.AY48
M_1_DQ40: U24.T13 U29.BC55
M_1_DQ41: U24.R13 U29.BC57
M_1_DQ42: U24.P13 U29.BE55
M_1_DQ43: U24.T14 U29.BD54
M_1_DQ44: U24.N12 U29.AY58
M_1_DQ45: U24.N11 U29.AW55
